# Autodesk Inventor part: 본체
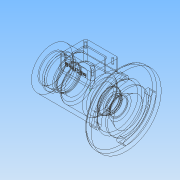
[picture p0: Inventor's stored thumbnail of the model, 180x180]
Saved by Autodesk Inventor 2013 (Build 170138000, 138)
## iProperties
Created: 2017-05
Part Number: 본체
Material: 알루미늄 6061
Document SubType Name: Modeling
Designer: Administrator
Density: 2.71 g/cm^3
Mass: 682.554 g
Surface Area: 617.779 cm^2
Volume: 251.865 cm^3
Author: Administrator
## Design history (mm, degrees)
sketch "스케치1"
  geometry: L1 (-57.5, 0)-(-57.5, 31); L2 (-57.5, 31)-(44.5, 31); L3 (44.5, 31)-(44.5, 53); L4 (44.5, 53)-(54.5, 53); L5 (54.5, 53)-(54.5, 31); L6 (54.5, 31)-(57.5, 31); L7 (57.5, 31)-(57.5, 0); L8 (57.5, 0)-(-57.5, 0); 2 further points
  constraints: 16 end point, 4 parallel, 2 coincident, 2 perpendicular, 1 collinear, 1 midpoint, 1 vertical
  dimensions: "d0" = 62 diameter of L2 L8; "d2" = 3 distance between parallel lines of L7 L5; "d3" = 10 distance of L3.end L4.end; "d4" = 115 distance of L7.end L1.start; "d5" = 106 diameter of L4 L8; "d6" = 62 diameter of L6 L8
revolve "회전1" sketch "스케치1" stored, may be unused: angle "d7" = 90 deg
hole "구멍1" diameter "d10" = 40.376; stored, may be unused: countersink angle "d14" = 90 deg, drill point angle "d16" = 0 deg; dims "d8" = 10, "d9" = 10, "d11" = 6, "d12" = 4, "d13" = 2, "d15" = 9
hole "구멍2" diameter "d19" = 40; stored, may be unused: countersink angle "d23" = 90 deg, drill point angle "d25" = 0 deg; dims "d20" = 6, "d21" = 48, "d22" = 3, "d24" = 12, "d98" = 10, "d99" = 10
hole "구멍3" diameter "d28" = 35; stored, may be unused: countersink angle "d32" = 90 deg, drill point angle "d34" = 0 deg; dims "d26" = 10, "d27" = 10, "d29" = 6, "d30" = 48, "d31" = 3, "d33" = 3.25
hole "구멍4" diameter "d37" = 37; stored, may be unused: countersink angle "d41" = 90 deg, drill point angle "d43" = 0 deg; dims "d35" = 10, "d36" = 10, "d38" = 6, "d39" = 48, "d40" = 3, "d42" = 1.75
hole "구멍5" diameter "d46" = 35; stored, may be unused: countersink angle "d50" = 90 deg, drill point angle "d52" = 0 deg; dims "d44" = 10, "d45" = 10, "d47" = 6, "d48" = 48, "d49" = 3, "d51" = 11
hole "구멍6" diameter "d55" = 52; stored, may be unused: countersink angle "d59" = 90 deg, drill point angle "d61" = 0 deg; dims "d53" = 10, "d54" = 10, "d56" = 6, "d57" = 48, "d58" = 3, "d60" = 38
hole "구멍7" diameter "d64" = 35; stored, may be unused: countersink angle "d68" = 90 deg, drill point angle "d70" = 0 deg; dims "d62" = 10, "d63" = 10, "d65" = 6, "d66" = 48, "d67" = 3, "d69" = 11
hole "구멍8" diameter "d73" = 33; stored, may be unused: countersink angle "d77" = 90 deg, drill point angle "d79" = 0 deg; dims "d71" = 10, "d72" = 10, "d74" = 6, "d75" = 48, "d76" = 3, "d78" = 5
sketch "스케치2"
  geometry: C1 r 22 at (0, 0); 1 further point
  constraints: 1 centre point, 1 coincident
  dimensions: "d80" = 44 diameter of C1
node "작업 평면1"
sketch "스케치3"
  geometry: C1 r 16 at (0, 0); 1 further point
  constraints: 1 centre point, 1 coincident
  dimensions: "d82" = 32 diameter of C1
sketch "스케치4"
  geometry: 1 further point
feature "로프트1" dims "d83" = 0, "d84" = 90 deg, "d85" = 0, "d86" = 90 deg
hole "구멍9" diameter "d89" = 20; stored, may be unused: countersink angle "d93" = 90 deg, drill point angle "d95" = 0 deg; dims "d90" = 6, "d91" = 25, "d92" = 7.3, "d94" = 10, "d96" = 10, "d97" = 10
fillet "모깎기1" dims "d100" = 3
node "작업 평면2"
sketch "스케치5"
  geometry: L1 (-26.5, 20)-(23.5, 20); L2 (23.5, 20)-(23.5, -20); L3 (23.5, -20)-(-26.5, -20); L4 (-26.5, -20)-(-26.5, 20); L5 (-57.5, -31)-(-57.5, 31) reference; L6 (-1.5, 20)-(-1.5, -20); 3 further points
  constraints: 10 end point, 4 midpoint, 2 horizontal alignment, 2 parallel, 1 horizontal, 1 perpendicular
  dimensions: "d102" = 50 distance of L1.start L1.end; "d104" = 40 distance of L3.end L1.start; "d106" = 56 distance between parallel lines of L5 L6
extrude "돌출1" join sketch "스케치5" stored distance "d107" = 10; taper "d108" = 0 deg
sketch "스케치7"
  geometry: L1 (-26.5, 20)-(23.5, 20) reference; L2 (23.5, 20)-(23.5, -20) reference; L3 (-17.5, 11)-(14.5, 11); L4 (14.5, 11)-(14.5, -11); L5 (14.5, -11)-(-17.5, -11); L6 (-17.5, -11)-(-17.5, 11); 5 further points
  constraints: 8 end point, 4 midpoint, 2 parallel, 1 horizontal, 1 horizontal alignment, 1 perpendicular, 1 vertical alignment
  dimensions: "d124" = 32 distance of L4.end L5.end; "d127" = 22 distance of L5.end L3.start
extrude "돌출3" cut sketch "스케치7" distance "d128" = 40; taper "d129" = 0 deg
sketch "스케치8"
  geometry: L1 (-17.5, 11)-(14.5, 11) reference; L2 (14.5, -11)-(-17.5, -11) reference; L3 (-1.5, 11)-(-1.5, -11); 5 further points
  constraints: 2 end point, 2 midpoint
  dimensions: "d130" = 41 distance of point (19, -15.5) point (-22, -15.5); "d132" = 31 distance of point (-22, 15.5) point (-22, -15.5); "d133" = 41 distance of point (19, 15.5) point (-22, 15.5); "d134" = 31 distance of point (19, -15.5) point (19, 15.5); "d135" = 20.5 distance from line of point (-22, 15.5) L3; "d136" = 15.5 vertical distance of point (0, 0) point (-22, 15.5); "d137" = 15.5 vertical distance of point (0, 0) point (19, 15.5); "d138" = 20.5 distance from line of L3 point (19, -15.5)
hole "구멍10" sketch "스케치8" at (-22, 15.5), (19, 15.5), (19, -15.5), (-22, -15.5) diameter "d139" = 2.459; stored, may be unused: countersink angle "d143" = 90 deg, drill point angle "d145" = 118 deg; dims "d140" = 6, "d141" = 25, "d142" = 7.3, "d144" = 8
fillet "모깎기2" dims "d146" = 3, "d147" = 0.3
chamfer "모따기2" distance "d151" = 0.7; stored, may be unused: second distance "d152" = 2, angle "d153" = 30 deg
chamfer "모따기3" distance "d154" = 1; stored, may be unused: second distance "d155" = 2, angle "d156" = 30 deg
sketch "스케치9"
  geometry: L1 (44, 0)-(0, 0) reference; L2 (-34, -75)-(-34, -13) reference; 2 further points
  constraints: 1 other
  dimensions: "d157" = 56 distance from line of point (22, -8) L2; "d158" = 8 distance from line of point (22, -8) L1
feature "엠보싱1" sketch "스케치9" dims "d35" = 10, "d159" = 0.5, "d160" = 0
sketch "스케치10"
  geometry: C1 r 31 at (0, 0) reference; C2 r 53 at (0, 0) reference; A1 r 4 centre (41.5, 0) between (37.5, 0) and (45.5, 0); A2 r 4 centre (-41.5, 0) between (-37.5, 0) and (-45.5, 0); A3 r 4 centre (0, -41.5) between (0, -37.5) and (0, -45.5); A4 r 4 centre (0, 41.5) between (0, 37.5) and (0, 45.5); A5 r 37.5 centre (0, 0) between (37.5, 0) and (0, 37.5); A6 r 37.5 centre (0, 0) between (-37.5, 0) and (0, -37.5); A7 r 45.5 centre (0, 0) between (45.5, 0) and (0, 45.5); A8 r 45.5 centre (0, 0) between (-45.5, 0) and (0, -45.5)
  constraints: 16 point on circle, 8 centre point, 8 tangent, 2 coincident, 2 horizontal alignment, 2 vertical alignment
  dimensions: "d166" = 37.5 radius of A6; "d167" = 45.5 radius of A8; "d168" = 37.5 radius of A5; "d169" = 45.5 radius of A7
extrude "돌출4" cut sketch "스케치10" distance "d170" = 10; taper "d171" = 0 deg
node "솔리드1"
other parameters: "d81" = -14, "d101" = 44, "d109" = 91, "d110" = 75, "d161" = 75, "d163" = 91, "d165" = 75
